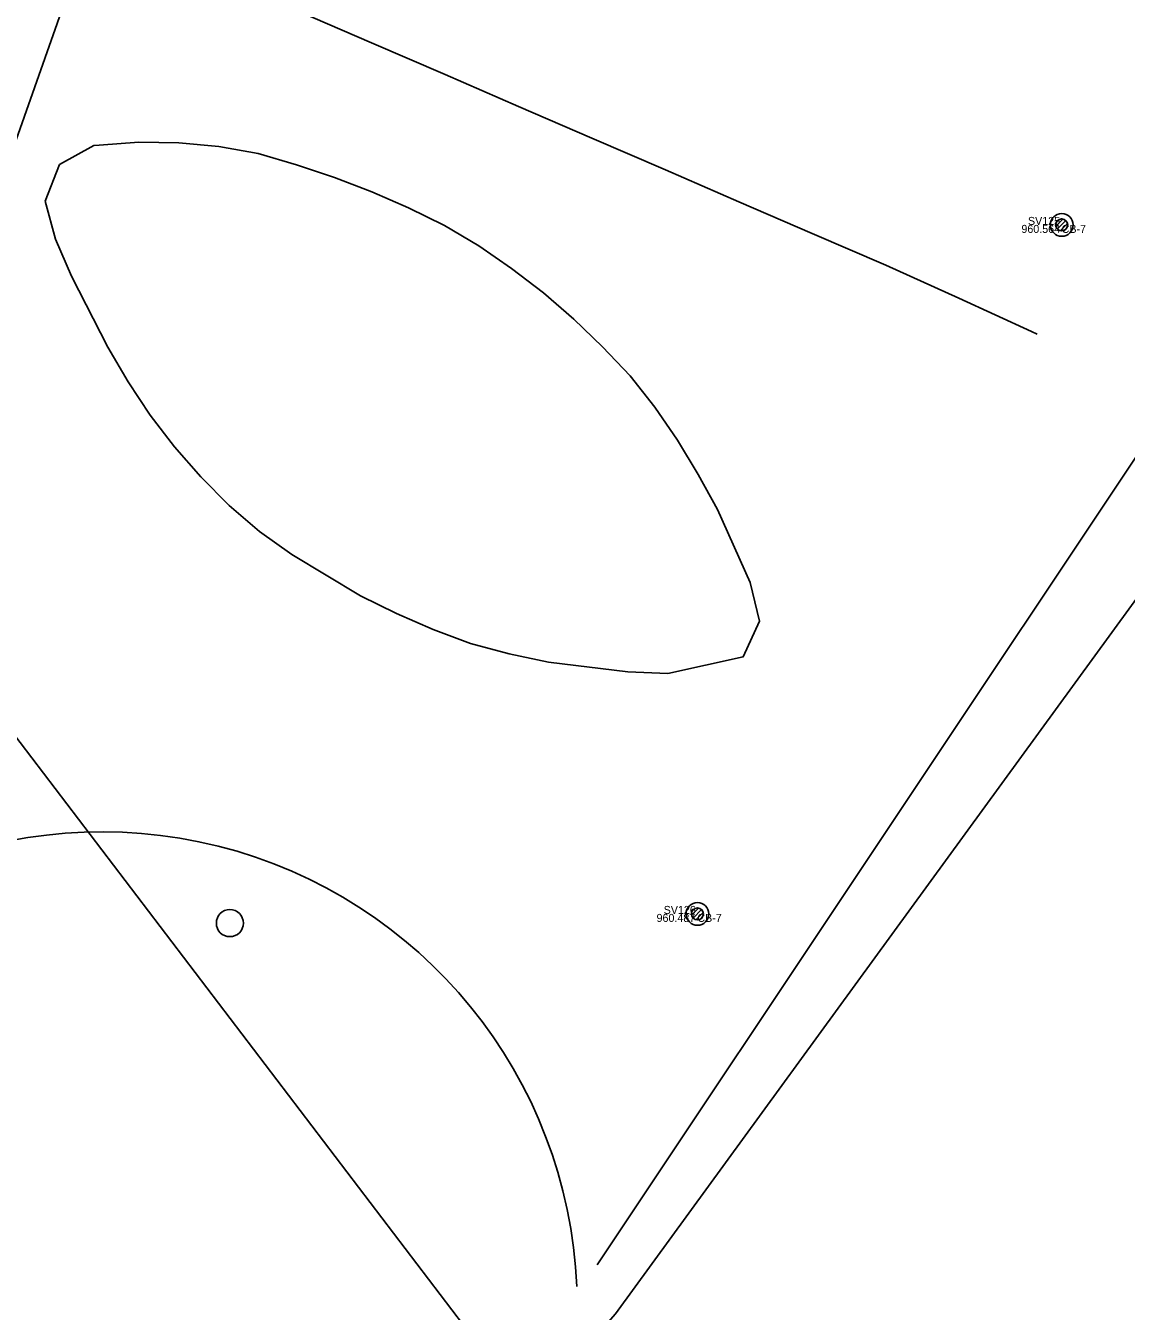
# Model space of a CAD drawing. Extents: x 2262025 to 2264532, y 740981 to 742724.
# Drawn here: x 2263063.3 to 2263200.9, y 741437.6 to 741598.2 of the extents above; entities that cross this region are included whole.
import ezdxf

# ---------------------------------------------------------------- set-up
doc = ezdxf.new("R2010")
doc.units = 0
for name, color, linetype in [('DR_X_Storm_Sewer', 7, 'Continuous'), ('DT_X_Break_Line', 7, 'Continuous'), ('GE_X_Alignment_100_Stations', 7, 'Continuous'), ('GE_X_Alignment_500_Bearings', 7, 'Continuous'), ('HY_X_Spring_Cells', 7, 'Continuous'), ('RS_Raster1', 7, 'Continuous'), ('RW_X_CL', 7, 'Continuous'), ('RW_X_CL_100_Curve_Data', 7, 'Continuous'), ('RW_X_CL_100_Stations', 7, 'Continuous'), ('SV_X_Text_Comment', 7, 'Continuous'), ('UT_X_Water', 7, 'Continuous')]:
    doc.layers.add(name, color=color, linetype=linetype)

msp = doc.modelspace()

# ---------------------------------------------------------------- linework, layer by layer
at = {"layer": 'DR_X_Storm_Sewer'}
msp.add_line((2262952, 741653.76), (2263353.07, 741127.49), dxfattribs=at)
at = {"layer": 'DT_X_Break_Line'}
msp.add_lwpolyline([(2263069.82, 741611.95), (2263078.99, 741607.98), (2263088.17, 741604.02), (2263097.35, 741600.05), (2263106.53, 741596.08), (2263115.71, 741592.11), (2263124.89, 741588.14), (2263134.07, 741584.17), (2263143.24, 741580.2), (2263152.42, 741576.23), (2263161.6, 741572.26), (2263170.78, 741568.3), (2263179.9, 741564.19), (2263188.99, 741560.03), (2263189.73, 741559.7)], dxfattribs=at)
at = {"layer": 'GE_X_Alignment_100_Stations'}
msp.add_circle((2263088.81, 741486.11), 1.69, dxfattribs=at)
at = {"layer": 'GE_X_Alignment_500_Bearings'}
msp.add_lwpolyline([(2263072.46, 741583.3), (2263077.45, 741583.66), (2263082.44, 741583.6), (2263087.42, 741583.13), (2263092.34, 741582.23), (2263097.14, 741580.85), (2263101.88, 741579.26), (2263106.55, 741577.47), (2263111.13, 741575.47), (2263115.62, 741573.26), (2263119.92, 741570.71), (2263124.03, 741567.88), (2263128, 741564.83), (2263131.79, 741561.57), (2263135.4, 741558.12), (2263138.83, 741554.48), (2263141.92, 741550.55), (2263144.75, 741546.43), (2263147.36, 741542.17), (2263149.75, 741537.77), (2263153.83, 741528.65), (2263155, 741523.85), (2263152.98, 741519.39), (2263143.53, 741517.31), (2263138.53, 741517.5), (2263128.62, 741518.72), (2263123.72, 741519.75), (2263118.9, 741521.06), (2263114.2, 741522.77), (2263109.62, 741524.77), (2263105.15, 741527), (2263096.57, 741532.14), (2263092.5, 741535.03), (2263088.71, 741538.29), (2263085.19, 741541.84), (2263081.9, 741545.6), (2263078.85, 741549.57), (2263076.1, 741553.74), (2263073.54, 741558.04), (2263069, 741566.94), (2263067.02, 741571.53), (2263065.72, 741576.31), (2263067.53, 741580.87), (2263071.82, 741583.23), (2263072.46, 741583.3)], dxfattribs=at)
msp.add_arc((2263072.86, 741438.14), 59.38, 2.4818, 149.2858, dxfattribs=at)
at = {"layer": 'RS_Raster1'}
for points in [[(2262680.86, 741714.81), (2262661.07, 741645.79), (2262765.42, 741624.79), (2262779.22, 741624.19), (2262826.51, 741606.02), (2262832.34, 741584.41), (2262933.09, 741544.98), (2262975.25, 741475.03), (2263024.25, 741455.82), (2263090.74, 741384.5), (2263137.01, 741437.31), (2263272.72, 741623.51), (2263304.66, 741651.89), (2263427.06, 741723.41), (2263444.69, 741740.07), (2263470.34, 741746.73), (2263467.01, 741806.69), (2263433.84, 741893.93), (2263732.51, 742061.95)], [(2263134.72, 741443.41), (2263205.64, 741549.67), (2263262.05, 741624.07)]]:
    msp.add_lwpolyline(points, dxfattribs=at)
at = {"layer": 'RW_X_CL_100_Curve_Data'}
for p, q in [((2263192.04, 741573.18), (2263192.92, 741574.06)), ((2263192.04, 741573.18), (2263192.92, 741574.06)), ((2263192.23, 741572.81), (2263193.29, 741573.87)), ((2263192.23, 741572.81), (2263193.29, 741573.87)), ((2263192.59, 741572.6), (2263193.5, 741573.51)), ((2263192.59, 741572.6), (2263193.5, 741573.51)), ((2263146.51, 741487.11), (2263147.39, 741487.99)), ((2263146.51, 741487.11), (2263147.39, 741487.99)), ((2263146.7, 741486.74), (2263147.76, 741487.8)), ((2263146.7, 741486.74), (2263147.76, 741487.8)), ((2263147.06, 741486.53), (2263147.97, 741487.44)), ((2263147.06, 741486.53), (2263147.97, 741487.44))]:
    msp.add_line(p, q, dxfattribs=at)
for centre, radius in [((2263192.78, 741573.33), 1.42), ((2263192.78, 741573.33), 1.42), ((2263192.77, 741573.33), 0.75), ((2263192.77, 741573.33), 0.75), ((2263192.78, 741573.33), 0.75), ((2263192.78, 741573.33), 0.75), ((2263147.25, 741487.26), 1.42), ((2263147.25, 741487.26), 1.42), ((2263147.24, 741487.26), 0.75), ((2263147.24, 741487.26), 0.75), ((2263147.25, 741487.26), 0.75), ((2263147.25, 741487.26), 0.75)]:
    msp.add_circle(centre, radius, dxfattribs=at)
at = {"layer": 'RW_X_CL_100_Stations'}
for p, q in [((2263192.77, 741573.33), (2263192.77, 741573.33)), ((2263192.77, 741573.33), (2263192.77, 741573.33)), ((2263192.77, 741573.33), (2263192.77, 741573.33)), ((2263192.77, 741573.33), (2263192.77, 741573.33)), ((2263192.77, 741573.33), (2263192.77, 741573.33)), ((2263192.77, 741573.33), (2263192.77, 741573.33)), ((2263192.78, 741574.74), (2263192.78, 741574.74)), ((2263192.78, 741574.74), (2263192.78, 741574.74)), ((2263192.78, 741571.91), (2263192.78, 741571.91)), ((2263192.78, 741571.91), (2263192.78, 741571.91)), ((2263147.25, 741488.67), (2263147.25, 741488.67)), ((2263147.25, 741488.67), (2263147.25, 741488.67)), ((2263147.24, 741487.26), (2263147.24, 741487.26)), ((2263147.24, 741487.26), (2263147.24, 741487.26)), ((2263147.24, 741487.26), (2263147.24, 741487.26)), ((2263147.24, 741487.26), (2263147.24, 741487.26)), ((2263147.24, 741487.26), (2263147.24, 741487.26)), ((2263147.24, 741487.26), (2263147.24, 741487.26)), ((2263147.25, 741485.84), (2263147.25, 741485.84)), ((2263147.25, 741485.84), (2263147.25, 741485.84))]:
    msp.add_line(p, q, dxfattribs=at)
for centre in [(2263192.77, 741573.33), (2263192.77, 741573.33), (2263147.24, 741487.26), (2263147.24, 741487.26)]:
    msp.add_circle(centre, 0.75, dxfattribs=at)
at = {"layer": 'UT_X_Water'}
msp.add_lwpolyline([(2263058.18, 741572.97), (2263085.82, 741651.25), (2263095.93, 741679.99), (2263097.95, 741685.82), (2263106.82, 741712.78), (2263147.36, 741828.66), (2263178.07, 741920.18), (2263217.98, 742032.49), (2263252.6, 742127.99), (2263295.63, 742247.6), (2263334.95, 742356.22), (2263370.78, 742449.55), (2263413.67, 742573.04), (2263421.38, 742593.43)], dxfattribs=at)

# ---------------------------------------------------------------- texts
at = {"layer": 'HY_X_Spring_Cells'}
for s, p in [('960.564', (2263187.74, 741572.33)), ('960.564', (2263187.74, 741572.33)), ('960.487', (2263142.14, 741486.26)), ('960.487', (2263142.14, 741486.26))]:
    msp.add_text(s, height=1, dxfattribs=at).set_placement(p)
at = {"layer": 'RW_X_CL'}
for p in [(2263192.77, 741572.33), (2263192.77, 741572.33), (2263147.24, 741486.26), (2263147.24, 741486.26)]:
    msp.add_text('CB-7', height=1, dxfattribs=at).set_placement(p)
at = {"layer": 'SV_X_Text_Comment'}
for s, p in [('SV125', (2263188.56, 741573.33)), ('SV125', (2263188.56, 741573.33)), ('SV126', (2263143.03, 741487.26)), ('SV126', (2263143.03, 741487.26))]:
    msp.add_text(s, height=1, dxfattribs=at).set_placement(p)

doc.saveas('drawing.dxf')
